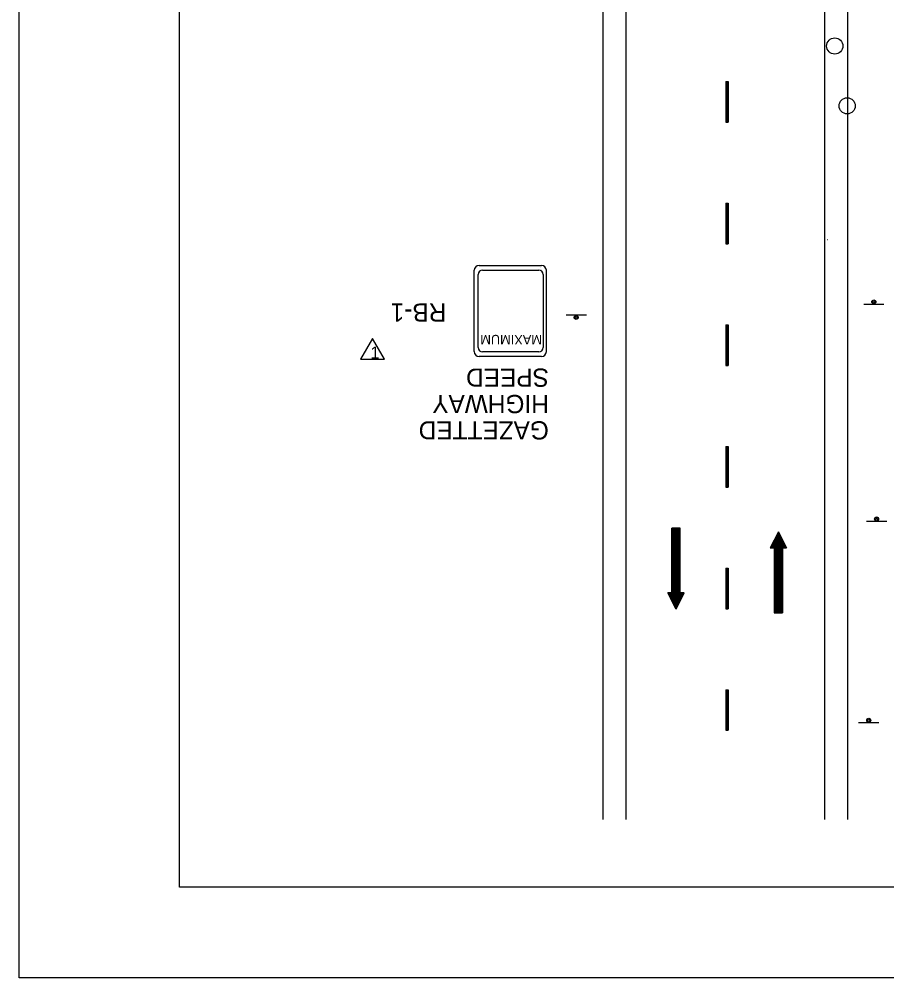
# Model space of a CAD drawing. Extents: x 1371 to 1587, y 163 to 442.
# Drawn here: x 1371 to 1474.5, y 163.4 to 277.8 of the extents above; entities that cross this region are included whole.
import ezdxf

# ---------------------------------------------------------------- set-up
doc = ezdxf.new("R2010")
doc.units = 0
for name, color, linetype in [('Level 1', 7, 'Continuous'), ('Level 10', 7, 'Continuous'), ('Level 44', 7, 'Continuous'), ('Level 60', 7, 'Continuous')]:
    doc.layers.add(name, color=color, linetype=linetype)

msp = doc.modelspace()

# ---------------------------------------------------------------- linework, layer by layer
at = {"layer": 'Level 1'}
msp.add_lwpolyline([(1413.1, 239.71), (1411.68, 237.24), (1414.52, 237.24)], close=True, dxfattribs=at)
at = {"layer": 'Level 10'}
for p, q in [((1440.59, 427.01), (1440.59, 182.32)), ((1443.31, 427.01), (1443.31, 182.32)), ((1467.02, 427.01), (1467.02, 182.32)), ((1469.76, 427.01), (1469.76, 182.32)), ((1455.26, 270.37), (1455.26, 265.53)), ((1455.26, 270.37), (1455.55, 270.37)), ((1455.33, 270.37), (1455.33, 265.53)), ((1455.41, 270.37), (1455.41, 265.53)), ((1455.48, 270.37), (1455.48, 265.53)), ((1455.55, 270.37), (1455.55, 265.53)), ((1455.26, 265.53), (1455.55, 265.53)), ((1455.26, 255.85), (1455.26, 251.02)), ((1455.26, 255.85), (1455.55, 255.85)), ((1455.33, 255.85), (1455.33, 251.02)), ((1455.41, 255.85), (1455.41, 251.02)), ((1455.48, 255.85), (1455.48, 251.02)), ((1455.55, 255.85), (1455.55, 251.02)), ((1455.26, 251.02), (1455.55, 251.02)), ((1467.36, 251.52), (1467.37, 251.52)), ((1455.26, 241.34), (1455.26, 236.5)), ((1455.26, 241.34), (1455.55, 241.34)), ((1455.33, 241.34), (1455.33, 236.5)), ((1455.41, 241.34), (1455.41, 236.5)), ((1455.48, 241.34), (1455.48, 236.5)), ((1455.55, 241.34), (1455.55, 236.5)), ((1455.26, 236.5), (1455.55, 236.5)), ((1455.26, 226.83), (1455.26, 221.99)), ((1455.26, 226.83), (1455.55, 226.83)), ((1455.33, 226.83), (1455.33, 221.99)), ((1455.41, 226.83), (1455.41, 221.99)), ((1455.48, 226.83), (1455.48, 221.99)), ((1455.55, 226.83), (1455.55, 221.99)), ((1455.26, 221.99), (1455.55, 221.99)), ((1448.83, 209.35), (1448.83, 217.09)), ((1449.79, 217.09), (1448.83, 217.09)), ((1448.83, 208.38), (1448.83, 217.09)), ((1448.95, 208.14), (1448.95, 217.09)), ((1449.07, 207.9), (1449.07, 217.09)), ((1449.19, 207.66), (1449.19, 217.09)), ((1449.31, 207.42), (1449.31, 217.09)), ((1449.43, 207.66), (1449.43, 217.09)), ((1449.55, 207.9), (1449.55, 217.09)), ((1449.67, 208.14), (1449.67, 217.09)), ((1449.79, 209.35), (1449.79, 217.09)), ((1449.79, 208.38), (1449.79, 217.09)), ((1461.53, 216.65), (1460.56, 214.72)), ((1461.4, 216.41), (1461.4, 206.98)), ((1461.53, 216.65), (1461.53, 206.98)), ((1461.53, 216.65), (1462.49, 214.72)), ((1461.65, 216.41), (1461.65, 206.98)), ((1460.8, 215.2), (1460.8, 214.72)), ((1460.92, 215.44), (1460.92, 214.72)), ((1461.04, 215.69), (1461.04, 206.98)), ((1461.16, 215.93), (1461.16, 206.98)), ((1461.28, 216.17), (1461.28, 206.98)), ((1461.77, 216.17), (1461.77, 206.98)), ((1461.89, 215.93), (1461.89, 206.98)), ((1462.01, 215.69), (1462.01, 206.98)), ((1462.13, 215.44), (1462.13, 214.72)), ((1462.25, 215.2), (1462.25, 214.72)), ((1460.56, 214.72), (1461.04, 214.72)), ((1460.68, 214.96), (1460.68, 214.72)), ((1461.04, 214.72), (1461.04, 206.98)), ((1462.01, 214.72), (1462.01, 206.98)), ((1462.01, 214.72), (1462.49, 214.72)), ((1462.37, 214.96), (1462.37, 214.72)), ((1455.26, 212.31), (1455.26, 207.47)), ((1455.26, 212.31), (1455.55, 212.31)), ((1455.33, 212.31), (1455.33, 207.47)), ((1455.41, 212.31), (1455.41, 207.47)), ((1455.48, 212.31), (1455.48, 207.47)), ((1455.55, 212.31), (1455.55, 207.47)), ((1449.31, 207.42), (1448.34, 209.35)), ((1448.83, 209.35), (1448.34, 209.35)), ((1448.46, 209.11), (1448.46, 209.35)), ((1448.59, 208.87), (1448.59, 209.35)), ((1448.71, 208.62), (1448.71, 209.35)), ((1449.31, 207.42), (1450.28, 209.35)), ((1450.28, 209.35), (1449.79, 209.35)), ((1449.91, 208.62), (1449.91, 209.35)), ((1450.04, 208.87), (1450.04, 209.35)), ((1450.16, 209.11), (1450.16, 209.35)), ((1455.26, 207.47), (1455.55, 207.47)), ((1461.04, 206.98), (1462.01, 206.98)), ((1455.26, 197.8), (1455.26, 192.96)), ((1455.26, 197.8), (1455.55, 197.8)), ((1455.33, 197.8), (1455.33, 192.96)), ((1455.41, 197.8), (1455.41, 192.96)), ((1455.48, 197.8), (1455.48, 192.96)), ((1455.55, 197.8), (1455.55, 192.96)), ((1455.26, 192.96), (1455.55, 192.96)), ((1440.59, 182.32), (1440.59, 182.32))]:
    msp.add_line(p, q, dxfattribs=at)
for centre in [(1468.25, 274.61), (1469.73, 267.47)]:
    msp.add_circle(centre, 0.968, dxfattribs=at)
at = {"layer": 'Level 44'}
for p, q in [((1425.82, 248.42), (1433.27, 248.42)), ((1425.24, 238.14), (1425.24, 247.85)), ((1425.72, 238.62), (1425.72, 247.35)), ((1426.24, 247.87), (1432.94, 247.87)), ((1433.14, 248.18), (1433.14, 248.18)), ((1433.23, 247.93), (1433.23, 247.93)), ((1433.46, 247.36), (1433.46, 247.35)), ((1433.46, 247.35), (1433.46, 238.62)), ((1433.84, 247.85), (1433.84, 238.14)), ((1433.84, 247.85), (1433.84, 247.85)), ((1471.7, 243.81), (1474.12, 243.81)), ((1438.62, 242.49), (1436.2, 242.49)), ((1432.94, 238.1), (1426.24, 238.1)), ((1433.27, 237.56), (1425.82, 237.56)), ((1472.03, 217.9), (1474.45, 217.9)), ((1471.09, 193.88), (1473.51, 193.88))]:
    msp.add_line(p, q, dxfattribs=at)
for centre, radius in [((1472.91, 244.08), 0.242), ((1472.91, 244.08), 0.121), ((1437.4, 242.22), 0.242), ((1437.4, 242.22), 0.121), ((1473.24, 218.17), 0.242), ((1473.24, 218.17), 0.121), ((1472.3, 194.15), 0.242), ((1472.3, 194.15), 0.121)]:
    msp.add_circle(centre, radius, dxfattribs=at)
for centre, radius, start, end in [((1425.82, 247.85), 0.575, 90, 180), ((1433.27, 247.85), 0.575, 360, 90), ((1426.24, 247.36), 0.517, 90, 180), ((1432.94, 247.36), 0.517, 360, 90), ((1425.82, 238.14), 0.575, 180, 270), ((1426.24, 238.62), 0.517, 180, 270), ((1432.94, 238.62), 0.517, 270, 360), ((1433.27, 238.14), 0.575, 270, 360)]:
    msp.add_arc(centre, radius, start, end, dxfattribs=at)
at = {"layer": 'Level 60'}
for points in [[(1370.95, 442.43), (1586.95, 442.43), (1586.95, 163.43), (1370.95, 163.43)], [(1390.08, 431.62), (1576.95, 431.62), (1576.95, 174.24), (1390.08, 174.24)]]:
    msp.add_lwpolyline(points, close=True, dxfattribs=at)

# ---------------------------------------------------------------- texts
at = {"layer": 'Level 1'}
msp.add_text('1', height=1.45, rotation=360, dxfattribs=at).set_placement((1412.87, 237.3))
at = {"layer": 'Level 10'}
for s, p in [('RB-1', (1421.91, 243.89)), ('SPEED', (1434.14, 236.13)), ('HIGHWAY', (1434.14, 232.98)), ('GAZETTED', (1434.14, 229.84))]:
    msp.add_text(s, height=2.177, rotation=180, dxfattribs=at).set_placement(p)
at = {"layer": 'Level 44'}
msp.add_text('MAXIMUM', height=1.139, rotation=180, dxfattribs=at).set_placement((1433.32, 240.14))

doc.saveas('drawing.dxf')
